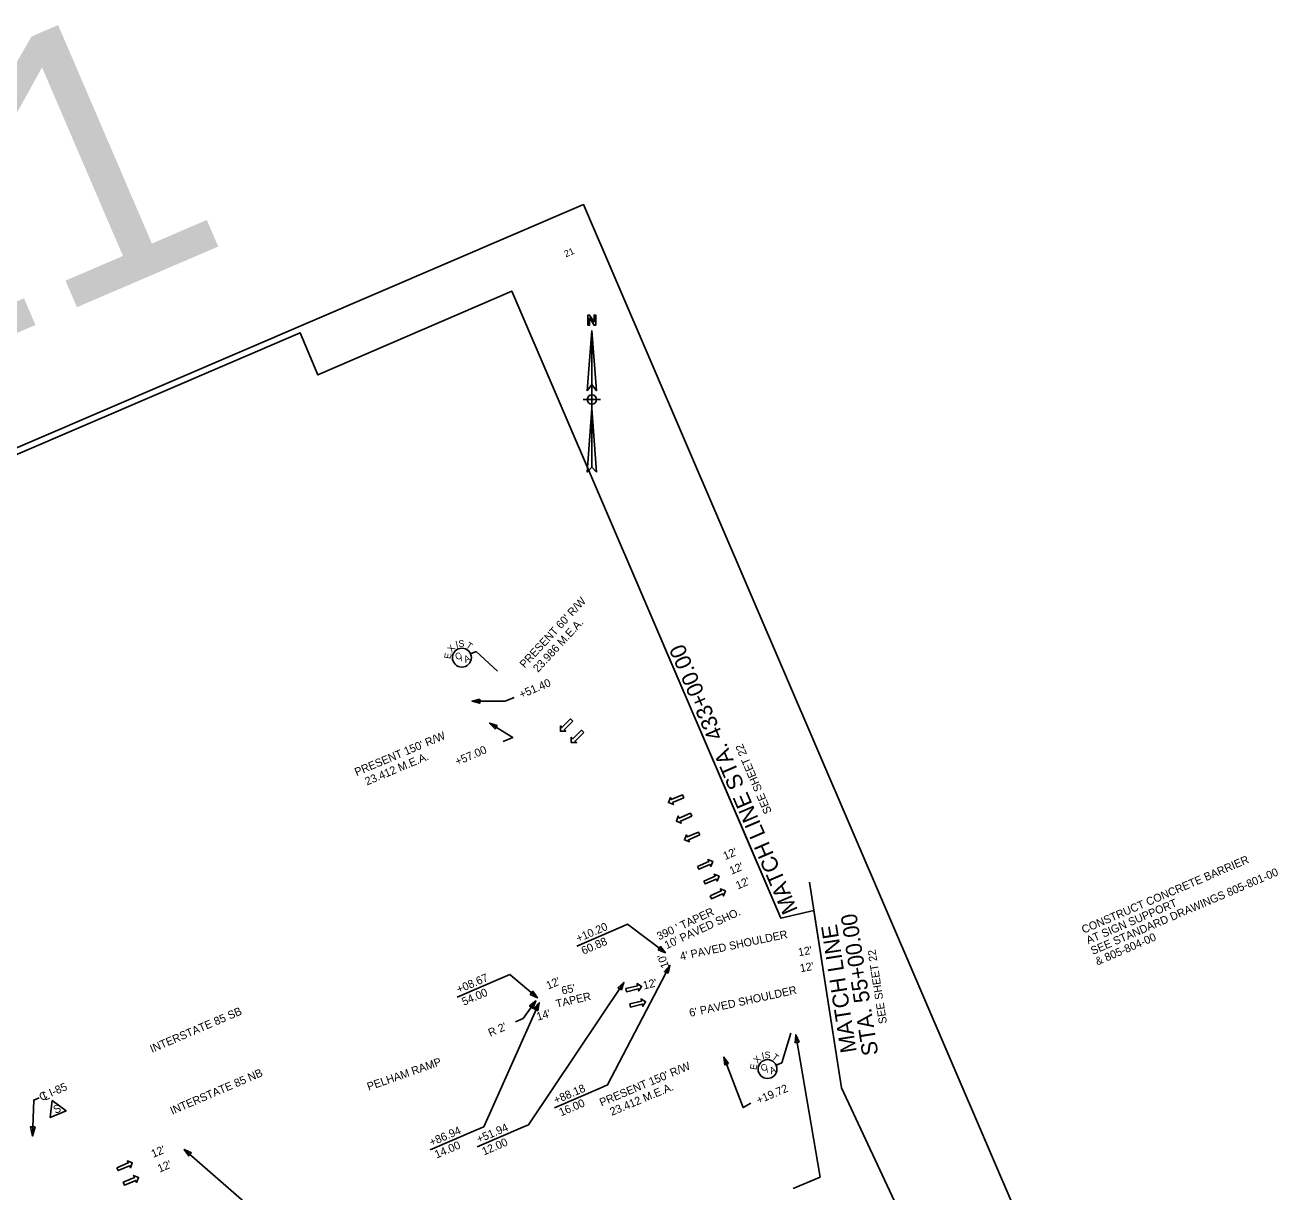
# Model space of a CAD drawing. Extents: x 1619612 to 1621672, y 1101722 to 1103419.
# Drawn here: x 1620732 to 1621672, y 1102544 to 1103419 of the extents above; entities that cross this region are included whole.
import ezdxf

# ---------------------------------------------------------------- set-up
doc = ezdxf.new("R2010")
doc.units = 0
for name, color, linetype in [('RD_EX_BldgApp', 7, 'Continuous'), ('RD_EX_DV_TX_Gov', 7, 'Continuous'), ('RD_EX_Fence_Other', 7, 'Continuous'), ('RD_EX_Misc', 7, 'Continuous'), ('RD_EX_Misc_Golf_Teebox', 7, 'Continuous'), ('RD_EX_RailRoad', 7, 'Continuous'), ('RD_EX_Road', 7, 'Continuous'), ('RD_EX_UT', 7, 'Continuous'), ('RD_EX_VEG', 7, 'Continuous'), ('RD_HC_Data', 7, 'Continuous')]:
    doc.layers.add(name, color=color, linetype=linetype)

msp = doc.modelspace()

# ---------------------------------------------------------------- linework, layer by layer
at = {"layer": 'RD_EX_BldgApp'}
for points in [[(1621098.78, 1102915.3), (1621091.97, 1102912.38), (1621067.27, 1102912.53)], [(1621090.5, 1102882.1), (1621097.77, 1102885.22), (1621080.43, 1102896.04)], [(1621307.93, 1102546.94), (1621328.19, 1102555.64), (1621309.99, 1102662.31)], [(1621276.29, 1102610.95), (1621270.6, 1102607.71), (1621256.17, 1102645.63)]]:
    msp.add_lwpolyline(points, dxfattribs=at)
for points in [[(1621073.07, 1102914.05), (1621067.27, 1102912.53), (1621073.05, 1102910.94)], [(1621086.17, 1102894.29), (1621080.43, 1102896.04), (1621084.53, 1102891.66)], [(1621312.49, 1102656.86), (1621309.99, 1102662.31), (1621309.43, 1102656.33)], [(1621259.68, 1102640.76), (1621256.17, 1102645.63), (1621256.78, 1102639.66)]]:
    msp.add_lwpolyline(points, close=True, dxfattribs=at)
at = {"layer": 'RD_EX_DV_TX_Gov'}
msp.add_lwpolyline([(1620737.67, 1102586.33), (1620738.62, 1102613.38), (1620742.65, 1102615.11)], dxfattribs=at)
msp.add_lwpolyline([(1620739.63, 1102593.16), (1620736.2, 1102593.28), (1620737.67, 1102586.33)], close=True, dxfattribs=at)
at = {"layer": 'RD_EX_Fence_Other'}
msp.add_lwpolyline([(1619611.56, 1102624.27), (1621150.78, 1103284.88), (1621528.02, 1102405.92), (1619988.8, 1101745.3)], close=True, dxfattribs=at)
at = {"layer": 'RD_EX_Misc'}
for points in [[(1621142.84, 1102897.48), (1621141.15, 1102899.18), (1621134.64, 1102892.72), (1621133.49, 1102893.87), (1621133.48, 1102889.87), (1621137.48, 1102889.86), (1621136.33, 1102891.01)], [(1621150.97, 1102889.02), (1621149.28, 1102890.72), (1621142.77, 1102884.26), (1621141.63, 1102885.42), (1621141.61, 1102881.42), (1621145.61, 1102881.4), (1621144.46, 1102882.56)], [(1621226.01, 1102840.02), (1621225.06, 1102842.23), (1621216.63, 1102838.61), (1621215.99, 1102840.11), (1621214.51, 1102836.39), (1621218.22, 1102834.91), (1621217.58, 1102836.41)], [(1621231.94, 1102826.2), (1621231, 1102828.4), (1621222.57, 1102824.78), (1621221.93, 1102826.28), (1621220.44, 1102822.57), (1621224.16, 1102821.08), (1621223.51, 1102822.58)], [(1621237.99, 1102812.11), (1621237.04, 1102814.32), (1621228.61, 1102810.7), (1621227.97, 1102812.2), (1621226.49, 1102808.48), (1621230.2, 1102807), (1621229.56, 1102808.5)], [(1621236.28, 1102788.61), (1621237.23, 1102786.4), (1621245.66, 1102790.02), (1621246.3, 1102788.53), (1621247.78, 1102792.24), (1621244.07, 1102793.72), (1621244.71, 1102792.23)], [(1621241.02, 1102777.58), (1621241.96, 1102775.38), (1621250.39, 1102779), (1621251.03, 1102777.5), (1621252.52, 1102781.21), (1621248.8, 1102782.7), (1621249.45, 1102781.2)], [(1621245.75, 1102766.56), (1621246.7, 1102764.35), (1621255.13, 1102767.97), (1621255.77, 1102766.47), (1621257.25, 1102770.19), (1621253.54, 1102771.67), (1621254.18, 1102770.17)], [(1621182.45, 1102696.94), (1621183.01, 1102694.61), (1621191.93, 1102696.76), (1621192.31, 1102695.18), (1621194.39, 1102698.59), (1621190.98, 1102700.68), (1621191.36, 1102699.09)], [(1621185.46, 1102685.44), (1621186.02, 1102683.1), (1621194.93, 1102685.26), (1621195.32, 1102683.67), (1621197.4, 1102687.09), (1621193.99, 1102689.17), (1621194.37, 1102687.59)], [(1620800.99, 1102562.61), (1620801.93, 1102560.41), (1620810.36, 1102564.02), (1620811, 1102562.53), (1620812.49, 1102566.24), (1620808.77, 1102567.73), (1620809.41, 1102566.23)], [(1620805.68, 1102551.69), (1620806.62, 1102549.48), (1620815.05, 1102553.1), (1620815.69, 1102551.6), (1620817.18, 1102555.32), (1620813.46, 1102556.8), (1620814.1, 1102555.31)]]:
    msp.add_lwpolyline(points, close=True, dxfattribs=at)
at = {"layer": 'RD_EX_Misc_Golf_Teebox'}
for p, q in [((1621180.45, 1102743.75), (1621145.77, 1102728.86)), ((1621090.37, 1102705.27), (1621056.13, 1102690.58)), ((1621163.25, 1102622.32), (1621129.01, 1102607.63)), ((1621069.96, 1102590.72), (1621035.72, 1102576.02)), ((1621105.43, 1102592.99), (1621071.19, 1102578.3))]:
    msp.add_line(p, q, dxfattribs=at)
for points in [[(1621180.45, 1102743.75), (1621183.8, 1102745.18), (1621212.27, 1102723.77)], [(1621163.25, 1102622.32), (1621168.86, 1102624.73), (1621215.59, 1102714.28)], [(1621090.37, 1102705.27), (1621095.7, 1102707.56), (1621116.26, 1102690.05)], [(1621105.43, 1102592.99), (1621109.69, 1102594.82), (1621181.18, 1102701.57)], [(1621069.96, 1102590.72), (1621076.03, 1102593.32), (1621117.6, 1102686.29)], [(1621099.78, 1102672.1), (1621105.5, 1102674.55), (1621115.11, 1102687.7)], [(1621014.93, 1102471.29), (1620986.07, 1102458.9), (1620851.43, 1102576.39)]]:
    msp.add_lwpolyline(points, dxfattribs=at)
for points in [[(1621206.7, 1102726.01), (1621212.27, 1102723.77), (1621208.57, 1102728.49)], [(1621214.28, 1102708.42), (1621215.59, 1102714.28), (1621211.53, 1102709.86)], [(1621179.25, 1102695.89), (1621181.18, 1102701.57), (1621176.67, 1102697.62)], [(1621110.84, 1102692.62), (1621116.26, 1102690.05), (1621112.85, 1102694.99)], [(1621112.94, 1102682.1), (1621115.11, 1102687.7), (1621110.44, 1102683.93)], [(1621116.65, 1102680.36), (1621117.6, 1102686.29), (1621113.81, 1102681.63)], [(1620752.44, 1102613.11), (1620750.9, 1102600.18), (1620762.87, 1102605.32)], [(1620856.82, 1102573.75), (1620851.43, 1102576.39), (1620854.77, 1102571.41)]]:
    msp.add_lwpolyline(points, close=True, dxfattribs=at)
at = {"layer": 'RD_EX_RailRoad'}
msp.add_lwpolyline([(1620011.01, 1101947.11), (1619998.11, 1101917.63), (1620027.5, 1101908.69), (1620077.33, 1101792.57), (1621455.74, 1102384.16), (1621344.3, 1102622.52), (1621323.62, 1102755.47), (1621298.88, 1102749.66), (1621097.02, 1103220), (1620951.48, 1103157.13), (1620938.43, 1103188.78), (1619705.25, 1102659.52)], close=True, dxfattribs=at)
msp.add_lwpolyline([(1620011.01, 1101947.11), (1619998.11, 1101917.63), (1620027.5, 1101908.69), (1620077.33, 1101792.57), (1621455.74, 1102384.16), (1621344.3, 1102622.52), (1621323.62, 1102755.47), (1621298.88, 1102749.66), (1621097.02, 1103220), (1620951.48, 1103157.13), (1620938.43, 1103188.78), (1619705.25, 1102659.52)], close=True, dxfattribs=at)
at = {"layer": 'RD_EX_UT'}
for p, q in [((1621157.1, 1103190.54), (1621153.68, 1103145.23)), ((1621157.1, 1103149.88), (1621153.68, 1103145.23)), ((1621157.1, 1103149.88), (1621157.1, 1103132.04)), ((1621163.62, 1103138.65), (1621150.65, 1103138.65)), ((1621157.1, 1103132.04), (1621160.52, 1103084.2)), ((1621160.52, 1103084.2), (1621157.1, 1103088.03))]:
    msp.add_line(p, q, dxfattribs=at)
msp.add_lwpolyline([(1621160.04, 1103194.37), (1621158.81, 1103194.37), (1621155.39, 1103199.84), (1621155.39, 1103199.02), (1621155.39, 1103194.37), (1621154.16, 1103194.37), (1621154.16, 1103201.96), (1621155.39, 1103201.96), (1621158.81, 1103196.9), (1621158.81, 1103197.31), (1621158.81, 1103201.96), (1621160.04, 1103201.96), (1621160.04, 1103194.37)], dxfattribs=at)
for points in [[(1621157.1, 1103190.54), (1621160.52, 1103145.23), (1621157.1, 1103149.88)], [(1621157.1, 1103132.04), (1621157.1, 1103088.03), (1621153.68, 1103084.2)]]:
    msp.add_lwpolyline(points, close=True, dxfattribs=at)
msp.add_circle((1621157.13, 1103138.65), 3.45, dxfattribs=at)
at = {"layer": 'RD_EX_VEG'}
msp.add_line((1621344.3, 1102622.52), (1621320.32, 1102776.71), dxfattribs=at)
msp.add_lwpolyline([(1621298.88, 1102749.66), (1621270.78, 1102815.13), (1621211.62, 1102952.97)], dxfattribs=at)
at = {"layer": 'RD_HC_Data'}
for p, q in [((1621066.14, 1102947.9), (1621070.34, 1102949.71)), ((1621070.34, 1102949.71), (1621086.43, 1102934.91)), ((1621299.55, 1102641.21), (1621306.21, 1102663.52)), ((1621295.34, 1102639.4), (1621299.55, 1102641.21))]:
    msp.add_line(p, q, dxfattribs=at)
for centre in [(1621059.63, 1102945.11), (1621288.83, 1102636.6)]:
    msp.add_circle(centre, 7.08, dxfattribs=at)

# ---------------------------------------------------------------- texts
at = {"layer": 'RD_EX_BldgApp'}
for s, rotation, p in [("PRESENT 60' R/W ", 47.28026, (1621106.71, 1102936.83)), ('  23.986 M.E.A.', 47.28026, (1621113.69, 1102930.38)), ('+51.40', 23.22835, (1621104.18, 1102914.35)), ("PRESENT 150' R/W ", 22.77639, (1620980.68, 1102856.23)), ('+57.00', 23.22835, (1621056.09, 1102864.06)), ('  23.412 M.E.A.', 22.77639, (1620984.36, 1102847.47)), ("PRESENT 150' R/W ", 22.77639, (1621164.33, 1102608.49)), ('  23.412 M.E.A.', 22.77639, (1621168.01, 1102599.73)), ('+19.72', 23.22835, (1621282.06, 1102610.16))]:
    msp.add_text(s, height=6, rotation=rotation, dxfattribs=at).set_placement(p)
at = {"layer": 'RD_EX_DV_TX_Gov'}
for s, rotation, p in [('INTERSTATE 85 SB', 23.22168, (1620827.25, 1102648.66)), ('PELHAM RAMP', 19.39636, (1620989.75, 1102620.31)), ('INTERSTATE 85 NB', 23.22168, (1620842.43, 1102602.27)), ('C I-85', 23.22168, (1620744.19, 1102612.56)), ('L', 23.22168, (1620746.98, 1102612.86))]:
    msp.add_text(s, height=6, rotation=rotation, dxfattribs=at).set_placement(p)
at = {"layer": 'RD_EX_Misc_Golf_Teebox'}
for s, height, rotation, p in [('21', 5, 23.22835, (1621137.64, 1103245.24)), ("12'", 6, 23.23465, (1621257.04, 1102793.23)), ('CONSTRUCT CONCRETE BARRIER ', 6, 23.22835, (1621525.92, 1102738.07)), ("12'", 6, 23.23465, (1621261.78, 1102782.2)), ('SEE STANDARD DRAWINGS 805-801-00', 6, 23.22835, (1621532.74, 1102722.18)), ("12'", 6, 23.23465, (1621266.51, 1102771.18)), ("390 ' TAPER", 6, 24.99662, (1621207.49, 1102733.07)), ("10' PAVED SHO.", 6, 24.87716, (1621213.21, 1102726.43)), ('AT SIGN SUPPORT', 6, 23.22835, (1621529.33, 1102730.13)), ('+10.20', 6, 23.22835, (1621146.82, 1102731.49)), ("4' PAVED SHOULDER", 6, 11.88917, (1621223.79, 1102718.05)), ('& 805-804-00', 6, 23.22835, (1621536.15, 1102714.24)), ('60.88', 6, 23.22835, (1621150.77, 1102722.3)), ("12'", 6, 10.36756, (1621312.36, 1102721.15)), ("10'", 6, 108.66577, (1621215.03, 1102713.44)), ("12'", 6, 10.36756, (1621313.67, 1102709.17)), ('+08.67', 6, 23.22835, (1621057.18, 1102693.21)), ("12'", 6, 23.23465, (1621124.36, 1102696.15)), ("65' ", 6, 13.08452, (1621135.02, 1102692.35)), ("12'", 6, 13.95449, (1621196.21, 1102696.23)), ('54.00', 6, 23.22835, (1621061.12, 1102684.02)), ('TAPER', 6, 13.08452, (1621130.81, 1102682.5)), ("6' PAVED SHOULDER", 6, 12.30023, (1621230.82, 1102675.7)), ("14'", 6, 16.29291, (1621116.55, 1102672.85)), ("R 2'", 6, 23.22835, (1621080.89, 1102660.72)), ('+88.18', 6, 23.22835, (1621130.06, 1102610.26)), ('S', 6, 23.22835, (1620754.75, 1102602.92)), ('16.00', 6, 23.22835, (1621134, 1102601.07)), ('+51.94', 6, 23.22835, (1621072.24, 1102580.92)), ('+86.94', 6, 23.22835, (1621036.77, 1102578.65)), ("12'", 6, 23.23465, (1620828.19, 1102569.93)), ('14.00', 6, 23.22835, (1621040.71, 1102569.46)), ('12.00', 6, 23.22835, (1621076.18, 1102571.73)), ("12'", 6, 23.23465, (1620832.95, 1102558.85))]:
    msp.add_text(s, height=height, rotation=rotation, dxfattribs=at).set_placement(p)
at = {"layer": 'RD_EX_Road'}
msp.add_text('SHEET 21', height=200, rotation=23.22835, dxfattribs=at).set_placement((1619727.87, 1102760.21))
at = {"layer": 'RD_EX_VEG'}
for s, height, rotation, p in [('MATCH LINE STA. 433+00.00', 12, 113.22835, (1621311.76, 1102755.88)), ('SEE SHEET 22', 6, 113.22835, (1621292.17, 1102829.37)), ('STA. 55+00.00', 12, 98.84251, (1621371.94, 1102647.62)), ('MATCH LINE', 12, 98.84251, (1621355.7, 1102649.68)), ('SEE SHEET 22', 6, 98.84251, (1621378.39, 1102671.02))]:
    msp.add_text(s, height=height, rotation=rotation, dxfattribs=at).set_placement(p)
at = {"layer": 'RD_HC_Data'}
for s, rotation, p in [('X', 48.32187, (1621052.02, 1102948.72)), ('I', 13.1604, (1621055.49, 1102952.44)), ('S', 1.43991, (1621057.06, 1102953.13)), ('T', 326.27843, (1621062.15, 1102953.14)), ('E', 81.80899, (1621051.29, 1102943.92)), ('C', 23.2251, (1621055.78, 1102943.03)), ('/', 23.2251, (1621059.33, 1102942.26)), ('A', 23.2251, (1621062.32, 1102941.2)), ('X', 46.36972, (1621281.35, 1102640.47)), ('I', 11.20824, (1621284.94, 1102644.07)), ('S', 359.48775, (1621286.54, 1102644.71)), ('T', 324.32628, (1621291.62, 1102644.55)), ('E', 79.85684, (1621280.46, 1102635.7)), ('C', 23.2251, (1621284.98, 1102634.53)), ('/', 23.2251, (1621288.53, 1102633.76)), ('A', 23.2251, (1621291.52, 1102632.7))]:
    msp.add_text(s, height=5, rotation=rotation, dxfattribs=at).set_placement(p)

doc.saveas('drawing.dxf')
